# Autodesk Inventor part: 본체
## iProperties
Created: 2014-10
Part Number: 본체
Document SubType Name: Modeling
Designer: tw_037
Density: 2.71 g/cm^3
Material: 알루미늄-6061
Mass: 906.65 g
Surface Area: 1044.9 cm^2
Volume: 334.557 cm^3
Author: tw_037
